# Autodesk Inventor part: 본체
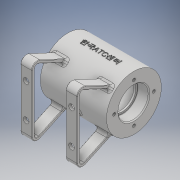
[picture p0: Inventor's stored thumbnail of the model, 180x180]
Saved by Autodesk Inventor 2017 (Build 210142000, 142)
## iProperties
Part Number: 본체
Material: 일반
Document SubType Name: Modeling
Designer: Administrator
Density: 1 g/cm^3
Appearance: 기본값
Author: Administrator
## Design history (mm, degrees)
sketch "스케치2"
  geometry: L1 (0, 16)-(0, 29); L2 (0, 29)-(70, 29); L3 (70, 29)-(70, 16); L4 (70, 16)-(58, 16); L5 (58, 16)-(58, 14); L6 (58, 14)-(56, 14); L7 (56, 14)-(56, 21); L8 (56, 21)-(14, 21); L9 (14, 21)-(14, 14); L10 (14, 14)-(12, 14); L11 (12, 14)-(12, 16); L12 (12, 16)-(0, 16); L13 (0, 0)-(70, 0)
  constraints: 26 end point, 8 perpendicular, 6 point on line, 1 horizontal, 1 vertical
  dimensions: "d1" = 70 distance of L1.end L2.end; "d2" = 42 diameter of L8 L13; "d3" = 12 distance of L11.end L1.start; "d4" = 12 distance of L3.end L4.end; "d5" = 2 distance of L5.end L6.end; "d6" = 42 distance of L7.end L8.end; "d7" = 58 diameter of L2 L13; "d8" = 32 diameter of L12 L13; "d9" = 28 diameter of L10 L13
revolve "회전1" sketch "스케치2" stored, may be unused: angle "d10" = 90 deg
sketch "스케치3"
  geometry: 2 further points
  constraints: 1 vertical alignment
  dimensions: "d11" = 21 distance of point (0, 0) point (0, 21)
hole "구멍1" sketch "스케치3" at (0, 21) diameter "d12" = 3.242; stored, may be unused: countersink angle "d16" = 90 deg, drill point angle "d18" = 118 deg; dims "d13" = 8, "d14" = 4, "d15" = 2, "d17" = 10
sketch "스케치4"
  geometry: C1 r 1.621 at (0, 21) reference; 2 further points
  constraints: 1 coincident, 1 vertical alignment
hole "구멍2" sketch "스케치4" at (0, 21) diameter "d22" = 3.242; stored, may be unused: countersink angle "d26" = 90 deg, drill point angle "d28" = 118 deg; dims "d23" = 8, "d24" = 4, "d25" = 2, "d27" = 10
node "작업 평면1"
sketch "스케치5"
  geometry: C1 r 5 at (-35, 0); 1 further point
  constraints: 1 centre point, 1 horizontal alignment
  dimensions: "d33" = 10 diameter of C1; "d34" = 35 distance of point (0, 0) C1.centre
extrude "돌출1" join sketch "스케치5" stored distance "d35" = 10; taper "d36" = 0 deg
hole "구멍3" diameter "d39" = 5.188; stored, may be unused: countersink angle "d43" = 90 deg, drill point angle "d45" = 118 deg; dims "d37" = 10, "d38" = 10, "d40" = 6, "d41" = 4, "d42" = 2, "d44" = 8
node "작업 평면3"
sketch "스케치6"
  geometry: L1 (17.993, -22.743)-(46.464, -36.02); L2 (55, -30.582)-(55, 30.582); L3 (46.464, 36.02)-(17.993, 22.743); L4 (20.438, 20.574)-(47.732, 33.301); L5 (52, 30.582)-(52, -30.582); L6 (47.732, -33.301)-(20.438, -20.574); C1 r 1.621 at (0, -21) reference; C2 r 1.621 at (21, 0) reference; C3 r 1.621 at (0, 21) reference; C4 r 1.621 at (-21, 0) reference; C5 r 16 at (0, 0) reference; A1 r 29 centre (0, 0) between (17.993, -22.743) and (17.993, 22.743) reference; A2 r 6 centre (49, -30.582) between (46.464, -36.02) and (55, -30.582); A3 r 6 centre (49, 30.582) between (55, 30.582) and (46.464, 36.02); A4 r 3 centre (49, 30.582) between (52, 30.582) and (47.732, 33.301); A5 r 3 centre (49, -30.582) between (47.732, -33.301) and (52, -30.582); 4 further points
  constraints: 12 end point, 12 point on circle, 4 centre point, 4 point on line, 4 tangent, 1 equal radius, 1 horizontal alignment, 1 midpoint, 1 vertical, 2 other
  dimensions: "d48" = 55 distance from line of point (0, 0) L2; "d49" = 65 deg angle of L2 L1; "d50" = 65 deg angle of L2 L3; "d51" = 80 distance of point (55, -40) point (55, 40); "d52" = 6 radius of A2 (derived); "d53" = 3 distance between parallel lines of L2 L5; "d54" = 3 distance between parallel lines of L1 L6; "d55" = 3 distance between parallel lines of L3 L4
extrude "돌출2" join sketch "스케치6" distance "d56" = 12; taper "d57" = 0 deg
node "작업 평면4"
sketch "스케치7"
  geometry: L1 (-17.993, 22.743)-(-46.464, 36.02); L2 (-55, 30.582)-(-55, -30.582); L3 (-46.464, -36.02)-(-17.993, -22.743); L4 (-20.438, -20.574)-(-47.732, -33.301); L5 (-52, -30.582)-(-52, 30.582); L6 (-47.732, 33.301)-(-20.438, 20.574); C1 r 1.621 at (0, -21) reference; C2 r 1.621 at (-21, 0) reference; C3 r 1.621 at (0, 21) reference; C4 r 1.621 at (21, 0) reference; C5 r 16 at (0, 0) reference; A1 r 29 centre (0, 0) between (-17.993, 22.743) and (-17.993, -22.743) reference; A2 r 6 centre (-49, 30.582) between (-46.464, 36.02) and (-55, 30.582); A3 r 6 centre (-49, -30.582) between (-55, -30.582) and (-46.464, -36.02); A4 r 3 centre (-49, -30.582) between (-52, -30.582) and (-47.732, -33.301); A5 r 3 centre (-49, 30.582) between (-47.732, 33.301) and (-52, 30.582); 4 further points
  constraints: 12 end point, 12 point on circle, 4 centre point, 4 point on line, 4 tangent, 1 equal radius, 1 horizontal alignment, 1 midpoint, 1 vertical, 2 other
  dimensions: "d59" = 80 distance of point (-55, 40) point (-55, -40); "d60" = 65 deg angle of L2 L1; "d61" = 65 deg angle of L2 L3; "d62" = 55 distance from line of point (0, 0) L2; "d63" = 6 radius of A2 (derived); "d64" = 3 distance between parallel lines of L2 L5; "d65" = 3 distance between parallel lines of L1 L6; "d66" = 3 distance between parallel lines of L4 L3
extrude "돌출3" join sketch "스케치7" distance "d67" = 12; taper "d68" = 0 deg
sketch "스케치8"
  geometry: L1 (0, 0)-(10.945, -30.07); L2 (0, 0)-(32, 0)
  constraints: 4 end point, 1 equal length, 1 horizontal
  dimensions: "d69" = 32 distance of L1.start L1.end; "d70" = 70 deg angle of L1 L2
node "작업 평면5"
sketch "스케치9"
  geometry: L1 (-17, -12.342)-(-5, -12.342) reference; L2 (-5, -12.342)-(-5, -15.218) reference; L3 (-5, -15.218)-(-17, -15.218) reference; L4 (-17, -15.218)-(-17, -12.342) reference; L5 (-17, 27.526)-(-5, 27.526) reference; L6 (-5, 27.526)-(-5, 26.323) reference; L7 (-5, 26.323)-(-17, 26.323) reference; L8 (-17, 26.323)-(-17, 27.526) reference; L9 (-53, 26.323)-(-65, 26.323) reference; L10 (-65, 26.323)-(-65, 27.526) reference; L11 (-65, 27.526)-(-53, 27.526) reference; L12 (-53, 27.526)-(-53, 26.323) reference; L13 (-53, -15.218)-(-65, -15.218) reference; L14 (-65, -15.218)-(-65, -12.342) reference; L15 (-65, -12.342)-(-53, -12.342) reference; L16 (-53, -12.342)-(-53, -15.218) reference; L17 (-70, -29)-(-70, 29) reference; L18 (0, -29)-(0, 29) reference; C1 r 6 at (-35, 0); 3 further points
  constraints: 2 horizontal alignment, 1 centre point, 1 midpoint, 1 other
  dimensions: "d71" = 12 diameter of C1; "d72" = 35 distance from line of C1.centre L18
extrude "돌출4" join sketch "스케치9" stored distance "d73" = 12; taper "d74" = 0 deg
hole "구멍4" diameter "d77" = 5.188; stored, may be unused: countersink angle "d81" = 90 deg, drill point angle "d83" = 118 deg; dims "d75" = 10, "d76" = 10, "d78" = 6, "d79" = 4, "d80" = 2, "d82" = 15
sketch "스케치10"
  geometry: L1 (-60, 61.164)-(-60, 0) reference; L2 (-60, 0)-(-60, -6) reference; L3 (0, -6)-(0, 0) reference; L4 (0, 61.164)-(0, 67.164) reference; C1 r 3 at (-54, 48.582); C2 r 3 at (-54, 12.582); C3 r 3 at (-6, 12.582); C4 r 3 at (-6, 48.582); 4 further points
  constraints: 4 centre point
  dimensions: "d84" = 6 diameter of C1; "d85" = 6 diameter of C2; "d86" = 6 diameter of C3; "d87" = 6 diameter of C4; "d88" = 36 distance of C2.centre C1.centre; "d89" = 6 distance from line of L1 C1.centre; "d90" = 6 distance from line of L2 C2.centre; "d91" = 6 distance from line of L3 C3.centre; "d92" = 6 distance from line of L4 C4.centre; "d93" = 36 distance of C4.centre C3.centre; "d94" = 18 vertical distance of point (-65, 30.582) C1.centre; "d95" = 18 vertical distance of point (-65, 30.582) C4.centre
extrude "돌출5" cut sketch "스케치10" distance "d96" = 12; taper "d97" = 0 deg
node "작업 평면6"
sketch "스케치11"
  geometry: L1 (0, 29)-(70, 29) reference; 2 further points
  constraints: 1 other
  dimensions: "d99" = 35 distance of point (35, 0) point (0, 0); "d100" = 29 distance from line of point (35, 0) L1
feature "엠보싱1" sketch "스케치11" dims "d1" = 70, "d2" = 42, "d3" = 12, "d4" = 12, "d5" = 2, "d6" = 42, "d7" = 58, "d8" = 32, "d9" = 28, "d101" = 0.5, "d102" = 0
fillet "모깎기1" dims "d103" = 1, "d104" = 0.5, "d105" = 3
fillet "모깎기2" dims "d106" = 3, "d107" = 0.3
chamfer "모따기1" distance "d108" = 1; stored, may be unused: second distance "d109" = 2, angle "d110" = 45 deg
chamfer "모따기2" distance "d111" = 1; stored, may be unused: second distance "d112" = 2, angle "d113" = 45 deg
sketch "스케치12"
  geometry: C1 r 1.5 at (0, 0); 1 further point
  constraints: 1 centre point
  dimensions: "d114" = 3 diameter of C1
extrude "돌출6" cut sketch "스케치12" distance "d115" = 20; taper "d116" = 0 deg
node "솔리드1"
pattern_circular "원형 패턴1" dims angle "d20" = 360 deg
pattern_circular "원형 패턴2" dims angle "d30" = 360 deg
node "투영된 루프1"
node "절단 모서리 투영1"
node "절단 모서리 투영2"
other parameters: "d32" = 32, "d47" = 5, "d58" = 65, "d98" = 44
